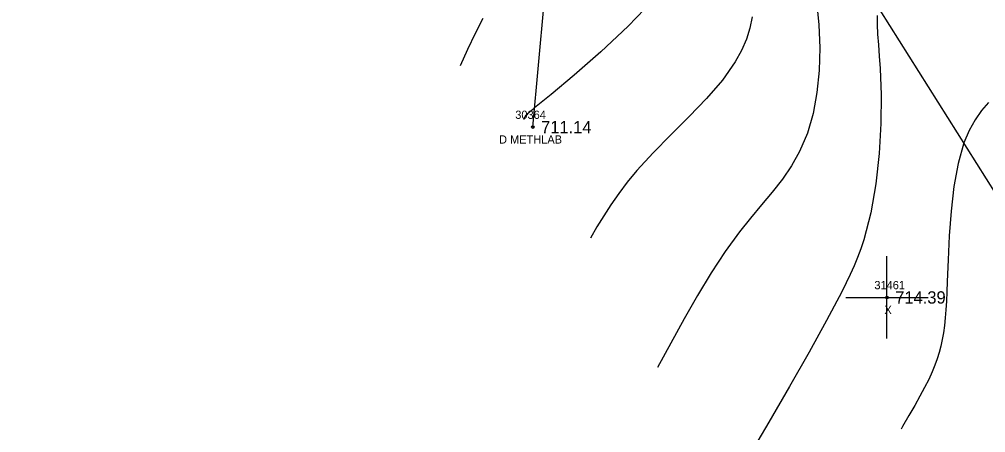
# Model space of a CAD drawing. Extents: x 1376587 to 1378239, y 1000335 to 1003031.
# Drawn here: x 1377457 to 1377574.4, y 1001264.8 to 1001315 of the extents above; entities that cross this region are included whole.
import ezdxf

# ---------------------------------------------------------------- set-up
doc = ezdxf.new("R2010")
doc.units = 0
for name, color, linetype in [('RD_DTM_Major1', 7, 'Continuous'), ('RD_DTM_Minor1', 7, 'Continuous'), ('RD_EX_Driveway', 7, 'Continuous'), ('RD_EX_Driveway_txCode', 7, 'Continuous'), ('RD_EX_Misc', 7, 'Continuous'), ('RD_EX_Misc_txCode', 7, 'Continuous'), ('RD_EX_Road', 7, 'Continuous'), ('RD_EX_TX_Driveway_ELEV', 7, 'Continuous'), ('RD_EX_TX_Misc_ELEV', 7, 'Continuous'), ('RD_SMD_Locator', 7, 'Continuous')]:
    doc.layers.add(name, color=color, linetype=linetype)

msp = doc.modelspace()

# ---------------------------------------------------------------- linework, layer by layer
at = {"layer": 'RD_DTM_Major1'}
for points in [[(1377513.32, 1001315.06), (1377512.37, 1001313.26), (1377511.46, 1001311.32), (1377510.55, 1001309.32)], [(1377574.79, 1001304.87), (1377573.95, 1001303.89), (1377573.16, 1001302.75), (1377572.44, 1001301.45), (1377571.81, 1001299.96), (1377571.1, 1001297.45), (1377570.59, 1001294.65), (1377570.25, 1001291.67), (1377570.03, 1001288.67), (1377569.88, 1001285.77), (1377569.78, 1001283.12), (1377569.73, 1001281.89), (1377569.67, 1001280.75), (1377569.6, 1001279.7), (1377569.52, 1001278.71), (1377569.43, 1001277.78), (1377569.31, 1001276.91), (1377569.17, 1001276.08), (1377569, 1001275.27), (1377568.8, 1001274.49), (1377568.56, 1001273.72), (1377568.28, 1001272.95), (1377567.96, 1001272.17), (1377567.52, 1001271.24), (1377567.02, 1001270.26), (1377566.45, 1001269.21), (1377565.82, 1001268.09), (1377565.12, 1001266.87), (1377564.35, 1001265.53), (1377564.16, 1001265.19)]]:
    msp.add_lwpolyline(points, dxfattribs=at)
at = {"layer": 'RD_DTM_Minor1'}
for points in [[(1377534.04, 1001317.34), (1377530.99, 1001314.15), (1377527.66, 1001311.03), (1377524.41, 1001308.2), (1377521.61, 1001305.86), (1377519.61, 1001304.22), (1377519.39, 1001304.03), (1377519.19, 1001303.86), (1377519.02, 1001303.72), (1377518.87, 1001303.59), (1377518.75, 1001303.48), (1377518.65, 1001303.37), (1377518.52, 1001303.24), (1377518.43, 1001303.13), (1377518.37, 1001303.03), (1377518.33, 1001302.95), (1377518.31, 1001302.88), (1377518.29, 1001302.81)], [(1377553.9, 1001317.18), (1377554.17, 1001314.31), (1377554.28, 1001311.51), (1377554.2, 1001308.76), (1377553.93, 1001306.09), (1377553.46, 1001303.53), (1377552.77, 1001301.13), (1377551.83, 1001298.9), (1377550.86, 1001297.18), (1377549.74, 1001295.56), (1377548.51, 1001293.99), (1377547.21, 1001292.44), (1377545.86, 1001290.84), (1377544.51, 1001289.16), (1377542.78, 1001286.77), (1377541.08, 1001284.19), (1377539.42, 1001281.45), (1377537.79, 1001278.59), (1377536.17, 1001275.66), (1377534.55, 1001272.69)], [(1377546.07, 1001315.27), (1377545.79, 1001313.91), (1377545.36, 1001312.55), (1377544.78, 1001311.17), (1377544.01, 1001309.79), (1377542.44, 1001307.59), (1377540.52, 1001305.37), (1377538.39, 1001303.15), (1377536.18, 1001300.94), (1377534.02, 1001298.76), (1377532.05, 1001296.62), (1377530.88, 1001295.21), (1377529.84, 1001293.82), (1377528.89, 1001292.45), (1377528.02, 1001291.1), (1377527.19, 1001289.75), (1377526.39, 1001288.41)], [(1377561.27, 1001315.43), (1377561.24, 1001314.34), (1377561.29, 1001313.16), (1377561.4, 1001311.89), (1377561.52, 1001310.5), (1377561.64, 1001309.01), (1377561.76, 1001305.82), (1377561.72, 1001302.32), (1377561.5, 1001298.66), (1377561.09, 1001294.98), (1377560.47, 1001291.45), (1377559.64, 1001288.2), (1377559.27, 1001287.1), (1377558.88, 1001286.05), (1377558.45, 1001285.02), (1377557.99, 1001283.99), (1377557.49, 1001282.96), (1377556.95, 1001281.89), (1377555.11, 1001278.39), (1377552.97, 1001274.53), (1377550.61, 1001270.38), (1377548.07, 1001266.03), (1377545.42, 1001261.53)]]:
    msp.add_lwpolyline(points, dxfattribs=at)
at = {"layer": 'RD_EX_Driveway'}
msp.add_lwpolyline([(1377519.4, 1001301.88), (1377521.45, 1001324.5), (1377530.82, 1001334.05), (1377536.05, 1001339.32), (1377540.93, 1001340.33)], dxfattribs=at)
at = {"layer": 'RD_EX_Misc'}
for p, q in [((1377562.45, 1001276.19), (1377562.45, 1001286.19)), ((1377557.45, 1001281.19), (1377567.45, 1001281.19))]:
    msp.add_line(p, q, dxfattribs=at)
at = {"layer": 'RD_EX_Road'}
msp.add_lwpolyline([(1377883.75, 1000788.5), (1377882.63, 1000790.22), (1377852.26, 1000839.6), (1377828.46, 1000879.31), (1377797, 1000930.66), (1377763.07, 1000986.65), (1377731.87, 1001037.81), (1377700.31, 1001089.98), (1377670.43, 1001138.24), (1377639.73, 1001190.03), (1377611.89, 1001234.23), (1377582.78, 1001282.57), (1377552.22, 1001331.03), (1377522.24, 1001382.35), (1377494.26, 1001430.19), (1377463.17, 1001481.14), (1377433.42, 1001531.29), (1377403.14, 1001580.98), (1377371.36, 1001632.19)], dxfattribs=at)
at = {"layer": 'RD_SMD_Locator'}
for centre in [(1377519.4, 1001301.88), (1377562.45, 1001281.19)]:
    msp.add_circle(centre, 0.15, dxfattribs=at)

# ---------------------------------------------------------------- texts
at = {"layer": 'RD_EX_Driveway_txCode'}
for s, p in [('30364', (1377517.26, 1001302.88)), ('D METHLAB', (1377515.29, 1001299.88))]:
    msp.add_text(s, height=1, dxfattribs=at).set_placement(p)
at = {"layer": 'RD_EX_Misc_txCode'}
for s, p in [('31461', (1377560.92, 1001282.19)), ('X', (1377562.14, 1001279.19))]:
    msp.add_text(s, height=1, dxfattribs=at).set_placement(p)
at = {"layer": 'RD_EX_TX_Driveway_ELEV'}
msp.add_text('711.14', height=1.5, dxfattribs=at).set_placement((1377520.4, 1001301.13))
at = {"layer": 'RD_EX_TX_Misc_ELEV'}
msp.add_text('714.39', height=1.5, dxfattribs=at).set_placement((1377563.45, 1001280.44))

doc.saveas('drawing.dxf')
